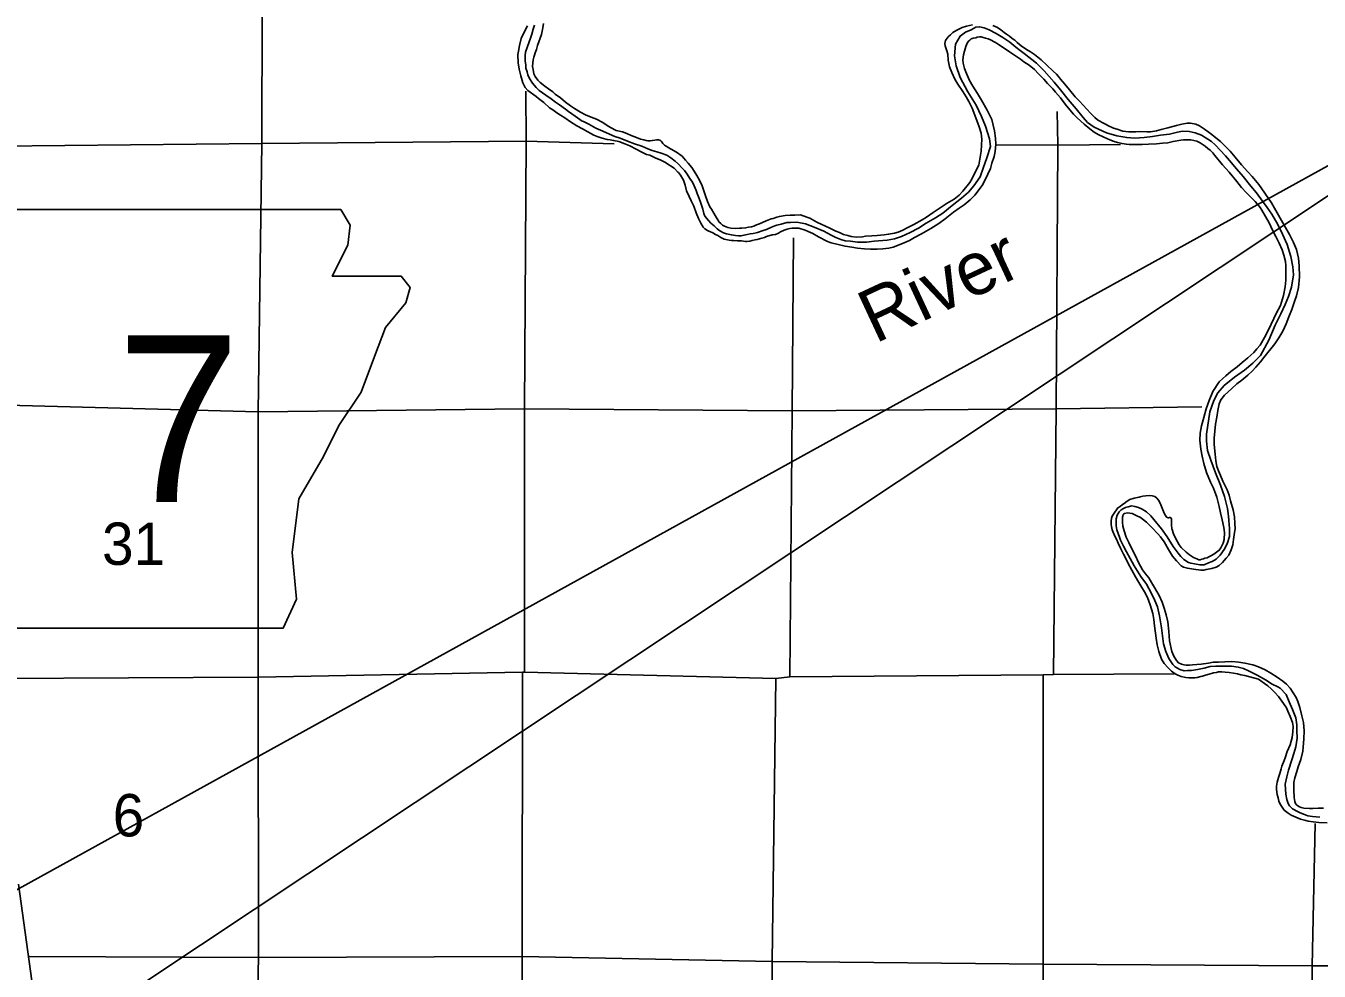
# Model space of a CAD drawing. Extents: x 369523 to 838377, y 495025 to 936819.
# Drawn here: x 671143 to 696948, y 532639 to 551489 of the extents above; entities that cross this region are included whole.
import ezdxf

# ---------------------------------------------------------------- set-up
doc = ezdxf.new("R2010")
doc.units = 0
for name, color, linetype in [('22', 7, 'Continuous'), ('DSN_DRFT_Common-Annotations', 7, 'Continuous'), ('Level 1', 7, 'Continuous'), ('Level 10', 7, 'Continuous'), ('Level 15', 7, 'Continuous'), ('Level 22', 7, 'Continuous'), ('Level 6', 7, 'Continuous')]:
    doc.layers.add(name, color=color, linetype=linetype)

msp = doc.modelspace()

# ---------------------------------------------------------------- linework, layer by layer
at = {"layer": '22'}
msp.add_lwpolyline([(669440, 547829), (669840, 545164), (669662, 541123), (670018, 540901), (670684, 540901), (670684, 539480), (676279, 539480), (676546, 540057), (676457, 540990), (676590, 542055), (677079, 542899), (677390, 543521), (677834, 544187), (678100, 544898), (678322, 545475), (678722, 545963), (678811, 546274), (678633, 546496), (677256, 546496), (677567, 547118), (677612, 547518), (677427, 547825)], close=True, dxfattribs=at)
at = {"layer": 'DSN_DRFT_Common-Annotations'}
msp.add_lwpolyline([(661941, 529285), (702469, 551647), (663912, 526047)], dxfattribs=at)
at = {"layer": 'Level 1'}
msp.add_lwpolyline([(670997, 534376), (671342, 531866)], dxfattribs=at)
at = {"layer": 'Level 10'}
for points in [[(686031, 547323), (685918, 547286), (685878, 547269), (685826, 547253), (685784, 547243), (685734, 547231), (685692, 547223), (685632, 547206), (685588, 547198), (685530, 547190), (685500, 547188), (685420, 547201), (685393, 547201), (685341, 547203), (685261, 547206), (685223, 547208), (685179, 547214), (685077, 547237), (685023, 547265), (685008, 547271), (684948, 547307), (684904, 547332), (684848, 547360), (684802, 547380), (684755, 547403), (684743, 547407), (684691, 547445), (684659, 547473), (684614, 547552), (684566, 547648), (684521, 547760), (684469, 547895), (684420, 548003), (684376, 548086), (684327, 548200), (684296, 548312), (684262, 548409), (684203, 548511), (684163, 548566), (684153, 548574), (684079, 548650), (684004, 548701), (683892, 548771), (683815, 548812), (683699, 548860), (683590, 548909), (683526, 548927), (683434, 548970), (683323, 549031), (683197, 549095), (683095, 549136), (682976, 549181), (682870, 549205), (682804, 549216), (682742, 549226), (682645, 549248), (682545, 549281), (682477, 549311), (682358, 549374), (682250, 549433), (682139, 549495), (682009, 549578), (681896, 549657), (681808, 549710), (681737, 549758), (681655, 549812), (681593, 549855), (681478, 549964), (681373, 550044), (681327, 550079), (681162, 550200), (681108, 550260), (681061, 550356), (681019, 550493), (680988, 550625), (680967, 550752), (680961, 550918), (680970, 550986), (680992, 551100), (681027, 551236), (681069, 551324), (681152, 551492)], [(681473, 551536), (681457, 551450), (681430, 551318), (681353, 551100), (681329, 551020), (681307, 550952), (681291, 550906), (681279, 550866), (681264, 550810), (681256, 550750), (681254, 550676), (681263, 550616), (681279, 550536), (681303, 550481), (681360, 550407), (681408, 550361), (681496, 550286), (681573, 550232), (681657, 550173), (681706, 550125), (681810, 550054), (681913, 549971), (682007, 549897), (682092, 549844), (682208, 549770), (682309, 549715), (682423, 549670), (682529, 549628), (682658, 549563), (682744, 549504), (682809, 549460), (682923, 549403), (683047, 549373), (683132, 549340), (683222, 549304), (683328, 549263), (683409, 549231), (683475, 549214), (683519, 549204), (683555, 549198), (683603, 549198), (683643, 549201), (683693, 549211), (683725, 549215), (683769, 549219), (683795, 549211), (683816, 549196), (683832, 549174), (683850, 549142), (683884, 549108), (683906, 549096), (683930, 549082), (683962, 549066), (684021, 549033), (684127, 548973), (684236, 548890), (684304, 548813), (684355, 548753), (684429, 548668), (684478, 548592), (684534, 548508), (684589, 548397), (684635, 548299), (684670, 548202), (684704, 548100), (684747, 547986), (684793, 547883), (684822, 547831), (684870, 547753), (684896, 547710), (684937, 547642), (684963, 547600), (684973, 547584), (685007, 547548), (685041, 547515), (685082, 547495), (685116, 547481), (685148, 547469), (685212, 547454), (685308, 547446), (685382, 547453)], [(690033, 551510), (689913, 551486), (689828, 551454), (689720, 551404)], [(694885, 542812), (694877, 542948), (694857, 543138), (694851, 543264), (694883, 543547), (694909, 543683), (694927, 543817), (694956, 543949), (694990, 544035), (695060, 544125), (695199, 544251), (695309, 544348), (695409, 544426), (695526, 544524), (695610, 544606), (695686, 544684), (695780, 544792), (695843, 544879), (696067, 545149), (696142, 545267), (696224, 545403), (696292, 545550), (696345, 545690), (696401, 545830), (696457, 545992), (696497, 546108), (696539, 546274), (696556, 546487), (696552, 546705), (696534, 546855), (696496, 547027), (696438, 547171), (696356, 547331), (696253, 547515), (696059, 547855), (695995, 547959), (695747, 548323), (695610, 548485), (695526, 548579), (695398, 548719), (695272, 548871), (695171, 548991), (695081, 549085), (694977, 549181), (694851, 549285), (694809, 549325), (694660, 549431), (694564, 549493), (694490, 549527), (694382, 549549), (694315, 549549), (694211, 549531), (694099, 549503), (693932, 549456), (693794, 549420), (693706, 549396), (693583, 549378), (693509, 549376), (693363, 549380), (693292, 549378), (693152, 549374), (693034, 549390), (692919, 549427), (692843, 549447), (692731, 549503), (692699, 549521), (692617, 549559), (692529, 549613), (692472, 549665), (692384, 549747), (692312, 549831), (692166, 549991), (692082, 550075), (691967, 550211), (691873, 550329), (691787, 550425), (691747, 550479), (691705, 550525), (691641, 550585), (691516, 550703), (691400, 550813), (691268, 550919), (691190, 550973), (691108, 551015), (691001, 551091), (690923, 551159), (690873, 551201), (690821, 551239), (690771, 551281), (690711, 551325), (690665, 551359), (690598, 551413), (690532, 551455), (690438, 551497)], [(689720, 551404), (689640, 551354), (689590, 551308), (689549, 551270), (689509, 551218), (689491, 551198), (689479, 551138), (689485, 551090), (689521, 550994), (689539, 550923), (689549, 550807), (689573, 550671), (689617, 550559), (689681, 550427), (689739, 550329), (689840, 550179), (689904, 550077), (689956, 549983), (690022, 549849), (690080, 549707), (690126, 549581), (690158, 549499), (690202, 549347), (690220, 549229), (690206, 548993), (690180, 548832), (690155, 548712), (690069, 548542), (690023, 548448), (689977, 548366), (689840, 548194), (689766, 548111), (689664, 548035), (689529, 547951), (689246, 547765), (689116, 547676), (689024, 547618), (688863, 547530), (688729, 547460), (688644, 547418), (688546, 547376), (688472, 547354), (688358, 547333), (688267, 547319), (688197, 547317), (688131, 547309), (688023, 547301), (687898, 547293), (687836, 547285), (687710, 547277), (687612, 547289), (687541, 547307), (687457, 547331), (687375, 547369), (687305, 547398), (687197, 547448), (687084, 547500), (687026, 547528), (686924, 547572), (686784, 547652), (686727, 547674), (686597, 547720), (686489, 547714), (686396, 547712), (686296, 547708), (686178, 547690), (686124, 547674), (686051, 547651), (686017, 547639)], [(694825, 544197), (694952, 544389), (695028, 544457), (695088, 544508), (695189, 544598), (695313, 544690), (695415, 544776), (695524, 544868), (695642, 544976), (695708, 545049), (695769, 545125), (695855, 545275), (695945, 545441), (696094, 545752), (696176, 545916), (696239, 546112), (696273, 546282), (696285, 546418), (696283, 546710), (696277, 546789), (696245, 546915), (696209, 547021), (696153, 547157), (696087, 547287), (696019, 547415), (695953, 547559), (695879, 547689), (695806, 547815), (695772, 547865), (695714, 547939), (695670, 547985), (695600, 548057), (695500, 548159), (695402, 548267), (695307, 548389), (695151, 548571), (695017, 548717), (694867, 548907), (694824, 548959), (694774, 549011), (694730, 549047), (694672, 549091), (694574, 549155), (694510, 549187), (694387, 549215), (694239, 549215), (694191, 549213), (694034, 549186), (693932, 549160), (693822, 549148), (693705, 549136), (693543, 549128), (693415, 549126), (693336, 549124), (693238, 549122), (693158, 549121), (693100, 549131), (693016, 549143), (692927, 549163), (692859, 549185), (692771, 549217), (692651, 549267), (692536, 549323), (692456, 549371), (692376, 549433), (692262, 549529), (692119, 549655), (692045, 549731), (691975, 549813), (691881, 549931), (691787, 550053), (691691, 550167), (691636, 550233), (691528, 550343), (691452, 550427), (691350, 550535), (691266, 550619), (691161, 550707), (691057, 550773), (690989, 550823), (690847, 550917), (690769, 550973), (690722, 551007), (690608, 551081), (690522, 551135), (690476, 551163), (690392, 551213), (690342, 551234), (690293, 551242), (690247, 551256), (690203, 551268), (690169, 551270), (690123, 551262), (690095, 551252), (690047, 551242), (690005, 551228), (689977, 551206), (689954, 551186), (689922, 551144), (689896, 551078), (689872, 550984)], [(689872, 550984), (689850, 550914), (689840, 550810), (689846, 550748), (689872, 550638), (689910, 550540), (689974, 550401), (690036, 550285), (690130, 550141), (690214, 550009), (690325, 549809), (690417, 549623), (690471, 549399), (690493, 549251), (690499, 549127), (690485, 548983), (690462, 548887), (690420, 548751), (690388, 548646), (690336, 548532), (690286, 548416), (690225, 548308), (690079, 548110), (689985, 548020), (689864, 547923), (689766, 547855), (689655, 547773), (689483, 547639), (689359, 547547), (689200, 547450), (689011, 547344), (688875, 547270), (688773, 547212), (688632, 547148), (688446, 547079), (688363, 547059), (688243, 547045), (688131, 547039), (687998, 547037), (687878, 547043), (687738, 547059), (687627, 547073), (687489, 547096), (687351, 547130), (687214, 547160), (687140, 547190), (686960, 547280), (686847, 547350), (686751, 547390), (686693, 547416), (686567, 547452), (686535, 547454), (686497, 547454), (686432, 547454), (686390, 547448), (686334, 547432), (686272, 547412), (686202, 547381), (686158, 547355), (686101, 547331), (686047, 547323), (686031, 547323)], [(685382, 547453), (685432, 547453), (685505, 547459), (685563, 547473), (685621, 547484), (685667, 547498), (685723, 547522), (685779, 547544), (685913, 547599), (686017, 547639)], [(693631, 539774), (693579, 539946), (693525, 540090), (693465, 540205), (693391, 540321), (693349, 540387), (693287, 540499), (693211, 540637), (693137, 540769), (693089, 540865), (693047, 540957), (692992, 541063), (692938, 541175), (692904, 541253), (692878, 541301), (692830, 541407), (692818, 541441), (692804, 541507), (692800, 541545), (692798, 541611), (692806, 541669), (692820, 541709), (692844, 541753), (692933, 541875), (692979, 541903), (693027, 541942), (693059, 541966), (693117, 542010), (693174, 542042), (693258, 542068), (693354, 542090), (693380, 542096), (693428, 542110), (693488, 542118), (693557, 542124), (693617, 542118), (693667, 542104), (693709, 542068), (693741, 542032), (693775, 541972), (693813, 541874), (693841, 541802), (693867, 541746), (693881, 541726), (693893, 541702), (693901, 541694), (693923, 541682), (693933, 541680), (693943, 541680), (693961, 541682), (693970, 541686), (693982, 541684), (693988, 541680), (694000, 541656), (694004, 541632), (694000, 541594), (694004, 541542), (694011, 541462), (694015, 541446), (694044, 541362), (694084, 541276), (694154, 541142), (694194, 541088), (694294, 540992), (694360, 540942), (694402, 540916), (694444, 540890), (694506, 540860), (694547, 540844), (694573, 540844), (694605, 540854), (694643, 540864), (694665, 540872), (694715, 540884), (694745, 540898), (694785, 540918), (694849, 540956), (694902, 540993), (694954, 541033), (694988, 541077), (695036, 541173), (695050, 541247), (695062, 541385), (695048, 541485), (695014, 541639), (694982, 541779), (694954, 541907), (694910, 542091), (694838, 542270), (694782, 542390), (694704, 542584), (694646, 542764), (694614, 542906), (694590, 543050), (694570, 543230), (694574, 543368), (694602, 543514), (694645, 543680), (694693, 543849), (694755, 544019), (694825, 544197)], [(696644, 537273), (696650, 537431), (696636, 537597), (696606, 537732), (696564, 537896), (696524, 538014), (696488, 538098), (696372, 538284), (696294, 538362), (696226, 538420), (696109, 538504), (695983, 538582), (695869, 538650), (695738, 538705), (695624, 538745), (695466, 538783), (695345, 538803), (695207, 538811), (695065, 538805), (694940, 538803), (694832, 538799), (694740, 538783), (694597, 538762), (694505, 538754), (694423, 538746), (694363, 538742), (694295, 538742), (694254, 538746), (694202, 538760), (694144, 538784), (694100, 538836), (694050, 538918), (694012, 539016), (693960, 539226), (693946, 539412), (693928, 539606), (693896, 539745), (693856, 539879), (693814, 539995), (693758, 540131), (693666, 540287), (693606, 540391), (693550, 540479), (693481, 540565), (693427, 540643), (693345, 540789), (693283, 540921), (693211, 541063), (693149, 541189), (693101, 541291), (693057, 541419), (693033, 541515), (693025, 541593), (693023, 541649), (693025, 541691), (693031, 541711), (693037, 541745), (693051, 541759), (693067, 541767), (693127, 541775), (693215, 541764), (693300, 541728), (693386, 541684), (693506, 541594), (693614, 541476), (693729, 541362), (693783, 541302), (693857, 541200), (693941, 541050), (694025, 540916), (694099, 540822), (694194, 540724), (694244, 540694), (694320, 540672), (694440, 540654), (694589, 540636), (694649, 540638), (694693, 540646), (694809, 540670), (694895, 540698), (694954, 540730), (695022, 540790), (695054, 540827), (695096, 540871), (695144, 540935), (695192, 541039), (695223, 541143), (695237, 541247), (695255, 541337), (695273, 541469), (695269, 541563), (695257, 541699), (695233, 541840), (695179, 542016), (695151, 542128), (695113, 542234), (695027, 542408), (694979, 542526), (694939, 542616), (694909, 542702), (694885, 542812)], [(697108, 535594), (696944, 535606), (696830, 535616), (696729, 535632), (696683, 535640), (696579, 535670), (696483, 535712), (696439, 535728), (696392, 535752), (696328, 535790), (696252, 535848), (696208, 535908), (696186, 535948), (696166, 535984), (696146, 536028), (696128, 536092), (696114, 536160), (696100, 536264), (696098, 536330), (696114, 536410), (696136, 536498), (696162, 536582), (696188, 536674), (696201, 536728), (696249, 536838), (696269, 536895), (696313, 537019), (696367, 537153), (696413, 537295), (696426, 537413), (696428, 537517), (696414, 537595), (696372, 537717), (696324, 537821), (696294, 537887), (696239, 537977), (696139, 538115), (696067, 538195), (695991, 538269), (695925, 538325), (695855, 538377), (695786, 538427), (695738, 538461), (695464, 538535), (695389, 538549), (695317, 538569), (695237, 538583), (695151, 538593), (695075, 538601), (695010, 538609), (694940, 538605), (694898, 538597), (694842, 538587), (694754, 538562), (694683, 538538), (694619, 538522), (694585, 538512), (694515, 538496), (694467, 538488), (694399, 538486), (694347, 538488), (694290, 538494), (694256, 538500), (694198, 538514), (694126, 538538), (694074, 538570), (694002, 538624), (693936, 538684), (693855, 538776), (693801, 538862), (693751, 539014), (693719, 539148), (693695, 539282), (693661, 539526), (693651, 539650), (693631, 539774)], [(697034, 535890), (696932, 535886), (696822, 535884), (696754, 535882), (696641, 535890), (696587, 535902), (696557, 535912), (696521, 535932), (696493, 535962), (696479, 535980), (696461, 536024), (696451, 536104), (696441, 536252), (696441, 536402), (696463, 536496), (696505, 536617), (696531, 536715), (696580, 536859), (696622, 537027), (696634, 537185), (696644, 537273)]]:
    msp.add_lwpolyline(points, dxfattribs=at)
at = {"layer": 'Level 15'}
for points in [[(670165, 538483), (670595, 538473), (675776, 538504), (681052, 538603), (681092, 538599), (686107, 538474)], [(686107, 538474), (686387, 538508), (691444, 538549), (691651, 538552), (694055, 538570)]]:
    msp.add_lwpolyline(points, dxfattribs=at)
at = {"layer": 'Level 22'}
for points in [[(675862, 554512), (675854, 549144), (675776, 543790), (675778, 538488), (675786, 532909), (675668, 527562), (675614, 522250), (675602, 518190)], [(681119, 550185), (681123, 549193), (681095, 543851), (681092, 538599)], [(691651, 538552), (691703, 543849), (691732, 549114), (691724, 549783)], [(670602, 549090), (675854, 549144), (681123, 549193), (682883, 549135)], [(690487, 549115), (691750, 549112), (692985, 549126)], [(686461, 547259), (686431, 543813), (686387, 538508)], [(681095, 543851), (675776, 543790), (670519, 543931)], [(681095, 543851), (686431, 543813), (691703, 543849), (694608, 543893)], [(681052, 538603), (681045, 532932), (681044, 527609), (680942, 522275), (680928, 516938), (680917, 516045)], [(686107, 538474), (686036, 532831), (686033, 527581), (685969, 522271), (685936, 516946), (685953, 514884)], [(691299, 513358), (691402, 516863), (691399, 522148), (691398, 527509), (691441, 532780), (691444, 538549)], [(696868, 535584), (696806, 532745), (696747, 527477), (696790, 522103), (696761, 516850), (696622, 511607)], [(671216, 532932), (675786, 532909), (681045, 532932), (686036, 532831)], [(686036, 532831), (691441, 532780), (696806, 532745), (699301, 532746)]]:
    msp.add_lwpolyline(points, dxfattribs=at)
at = {"layer": 'Level 6'}
for points in [[(681291, 551501), (681267, 551423), (681241, 551325), (681220, 551261), (681180, 551149), (681154, 551081), (681115, 550963), (681107, 550907), (681103, 550839), (681108, 550785), (681116, 550709), (681120, 550689), (681122, 550645), (681145, 550570), (681157, 550510), (681189, 550442), (681254, 550345), (681322, 550259), (681385, 550199), (681521, 550108), (681624, 550037), (681712, 549970), (681793, 549912), (681909, 549829), (681972, 549783), (682106, 549690), (682243, 549591), (682267, 549579), (682375, 549532), (682518, 549447), (682655, 549389), (682787, 549332), (682896, 549283), (682998, 549247), (683146, 549190), (683285, 549137), (683435, 549090), (683554, 549038), (683642, 549007), (683732, 548979), (683821, 548948), (683933, 548913), (684009, 548861), (684100, 548792), (684164, 548732), (684233, 548657), (684285, 548603), (684340, 548535), (684394, 548444), (684442, 548370), (684479, 548302), (684517, 548209), (684538, 548147), (684580, 548049), (684605, 547972), (684651, 547834), (684672, 547746), (684692, 547697), (684763, 547605), (684813, 547555), (684875, 547500), (684936, 547444), (684992, 547403), (685064, 547365), (685120, 547345), (685221, 547322), (685305, 547312), (685365, 547303), (685415, 547305), (685469, 547315), (685535, 547328), (685593, 547340), (685657, 547352), (685713, 547362), (685739, 547366), (685855, 547411), (685923, 547431), (686021, 547473)], [(691065, 550935), (690983, 550997), (690893, 551065), (690775, 551167), (690638, 551257), (690502, 551337), (690366, 551411), (690267, 551449), (690173, 551471), (690101, 551462), (690003, 551410), (689890, 551366), (689786, 551286), (689692, 551126), (689675, 550890), (689709, 550693), (689786, 550463), (689938, 550175), (690108, 549909), (690212, 549683), (690294, 549489), (690372, 549237), (690388, 549081), (690318, 548857), (690244, 548654), (690183, 548480), (690057, 548302), (689955, 548176), (689810, 548053), (689625, 547905), (689437, 547753), (689292, 547663), (689106, 547552), (688953, 547456), (688791, 547368), (688612, 547286), (688478, 547243), (688327, 547215), (688069, 547195), (687914, 547179), (687734, 547179), (687599, 547193), (687493, 547204), (687403, 547230), (687303, 547266), (687212, 547314), (687064, 547398), (686872, 547476), (686697, 547540), (686527, 547572), (686402, 547570), (686330, 547566), (686216, 547538), (686126, 547513), (686085, 547499), (686021, 547473)], [(692964, 541295), (692910, 541441), (692896, 541519), (692895, 541661), (692921, 541731), (692959, 541799), (693001, 541835), (693045, 541863), (693087, 541882), (693135, 541900), (693214, 541916), (693270, 541904), (693344, 541884), (693418, 541854), (693504, 541796), (693592, 541718), (693649, 541644), (693801, 541462), (693919, 541298), (694035, 541108), (694134, 540974), (694190, 540910), (694248, 540850), (694342, 540786), (694388, 540774), (694464, 540760), (694569, 540744), (694653, 540744), (694739, 540778), (694817, 540808), (694896, 540854), (694972, 540933), (695050, 541045), (695114, 541163), (695159, 541305), (695163, 541463), (695147, 541623), (695143, 541711), (695119, 541867), (695063, 542106), (694981, 542330), (694883, 542576), (694788, 542828), (694724, 543022), (694698, 543208), (694699, 543348), (694767, 543791), (694845, 544021), (694924, 544169), (695056, 544315), (695261, 544484), (695457, 544626), (695628, 544760), (695775, 544919), (695943, 545219), (696074, 545521), (696186, 545750), (696271, 545932), (696337, 546094), (696395, 546276), (696437, 546522), (696423, 546681), (696381, 546891), (696313, 547131), (696219, 547337), (696121, 547527), (696003, 547731), (695909, 547865), (695817, 547993), (695700, 548157), (695586, 548291), (695434, 548485), (695302, 548635), (695159, 548803), (695079, 548897), (694871, 549115), (694801, 549185), (694730, 549227), (694598, 549307), (694472, 549355), (694355, 549383), (694225, 549389), (694121, 549369), (693964, 549330), (693784, 549310), (693621, 549286), (693459, 549264), (693274, 549248), (693110, 549262), (692911, 549299), (692707, 549353), (692456, 549471), (692328, 549565), (692238, 549659), (692102, 549835), (691943, 550023), (691789, 550215), (691661, 550367), (691460, 550591), (691308, 550745), (691065, 550935)], [(696964, 535710), (696816, 535722), (696725, 535738), (696653, 535762), (696573, 535798), (696515, 535822), (696427, 535868), (696419, 535878), (696358, 535932), (696330, 535984), (696304, 536062), (696286, 536168), (696272, 536368), (696303, 536512), (696335, 536648), (696405, 536853), (696445, 536979), (696484, 537115), (696508, 537285), (696506, 537439), (696502, 537549), (696480, 537691), (696418, 537859), (696352, 538007), (696288, 538154), (696169, 538280), (696127, 538310), (696011, 538361), (695877, 538445), (695710, 538541), (695550, 538621), (695438, 538671), (695335, 538703), (695197, 538723), (695093, 538721), (694888, 538719), (694774, 538715), (694656, 538682), (694521, 538652), (694399, 538636), (694319, 538632), (694256, 538628), (694168, 538652), (694076, 538706), (694032, 538754), (693950, 538874), (693888, 539010), (693844, 539166), (693806, 539486), (693766, 539726), (693738, 539844), (693720, 539901), (693670, 540033), (693604, 540167), (693505, 540355), (693391, 540509), (693255, 540721), (693175, 540869), (693105, 541003), (693047, 541111), (692987, 541231), (692964, 541295)]]:
    msp.add_lwpolyline(points, dxfattribs=at)

# ---------------------------------------------------------------- texts
at = {"layer": '22'}
msp.add_text('7', height=3326, dxfattribs=at).set_placement((672956, 541992))
at = {"layer": 'Level 10'}
msp.add_text('River', height=1056, rotation=25, dxfattribs=at).set_placement((688087, 545146))
at = {"layer": 'Level 22'}
for s, height, p in [('31', 844.8, (672663, 540740)), ('6', 845, (672876, 535325))]:
    msp.add_text(s, height=height, dxfattribs=at).set_placement(p)

doc.saveas('drawing.dxf')
